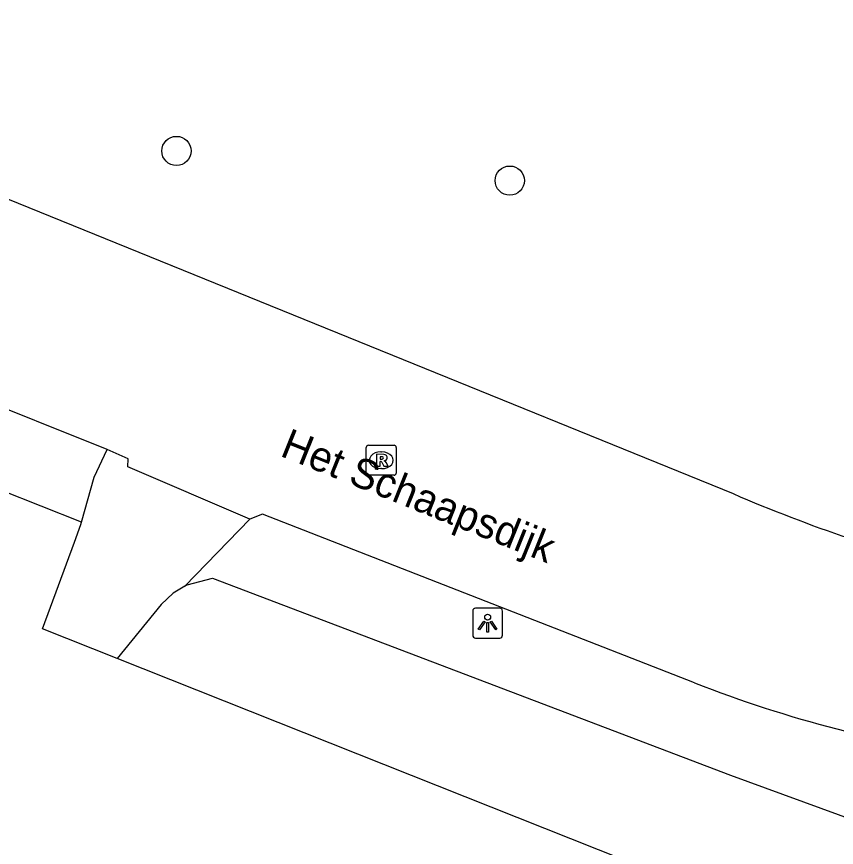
# Model space of a CAD drawing. Extents: x 156414 to 157775, y 382335 to 383765.
# Drawn here: x 156588.75 to 156616.15, y 383055.72 to 383083.48 of the extents above; entities that cross this region are included whole.
import ezdxf

# ---------------------------------------------------------------- set-up
doc = ezdxf.new("R2010")
doc.units = 0
for name, color, linetype in [('IMGEO_Boom', 7, 'Continuous'), ('IMGEO_Groenvoorziening', 7, 'Continuous'), ('IMGEO_Lichtpunt', 7, 'Continuous'), ('IMGEO_Openbare_ruimte_label', 7, 'Continuous'), ('IMGEO_Rijbaan_lokaal_gesloten', 7, 'Continuous'), ('IMGEO_Rioolput', 7, 'Continuous'), ('IMGEO_Voetpad_halfverhard', 7, 'Continuous')]:
    doc.layers.add(name, color=color, linetype=linetype)

msp = doc.modelspace()

# ---------------------------------------------------------------- linework, layer by layer
at = {"layer": 'IMGEO_Boom'}
for centre in [(156594.095, 383078.994), (156605.234, 383078.003)]:
    msp.add_circle(centre, 0.489, dxfattribs=at)
at = {"layer": 'IMGEO_Groenvoorziening'}
for points in [[(156590.919, 383066.585), (156586.871, 383068.195), (156585.286, 383064.741), (156563.007, 383025.818), (156595.152, 383012.104), (156611.363, 383016.16), (156615.246, 383017.093)], [(156594.376, 383064.451), (156594.453, 383064.497), (156595.3, 383064.715), (156612.61, 383058.128), (156628.734, 383052.234), (156630.668, 383048.465)], [(156629.772, 383039.352), (156627.811, 383047.838), (156592.108, 383062.029)]]:
    msp.add_lwpolyline(points, dxfattribs=at)
at = {"layer": 'IMGEO_Lichtpunt'}
for p, q in [((156603.995, 383063.616), (156603.995, 383062.809)), ((156603.995, 383063.616), (156603.995, 383062.809)), ((156604.897, 383063.711), (156604.089, 383063.711)), ((156604.897, 383063.711), (156604.089, 383063.711)), ((156604.991, 383062.809), (156604.991, 383063.616)), ((156604.991, 383062.809), (156604.991, 383063.616)), ((156604.089, 383062.715), (156604.897, 383062.715)), ((156604.089, 383062.715), (156604.897, 383062.715))]:
    msp.add_line(p, q, dxfattribs=at)
for points in [[(156604.369, 383063.28), (156604.408, 383063.252), (156604.22, 383062.99), (156604.182, 383063.017), (156604.369, 383063.28)], [(156604.471, 383063.232), (156604.518, 383063.232), (156604.518, 383062.91), (156604.471, 383062.91), (156604.471, 383063.232)], [(156604.581, 383063.252), (156604.619, 383063.279), (156604.806, 383063.017), (156604.767, 383062.989), (156604.581, 383063.252)]]:
    msp.add_lwpolyline(points, dxfattribs=at)
msp.add_circle((156604.494, 383063.414), 0.0994, dxfattribs=at)
for centre, start, end in [((156604.089, 383063.616), 90, 180), ((156604.089, 383063.616), 90, 180), ((156604.897, 383063.616), 0, 90), ((156604.897, 383063.616), 0, 90), ((156604.089, 383062.809), 180, 270), ((156604.089, 383062.809), 180, 270), ((156604.897, 383062.809), 270, 0), ((156604.897, 383062.809), 270, 360)]:
    msp.add_arc(centre, 0.0946, start, end, dxfattribs=at)
at = {"layer": 'IMGEO_Rijbaan_lokaal_gesloten'}
for points in [[(156573.541, 383083.485), (156575.164, 383082.79), (156612.694, 383067.543)], [(156591.78, 383069.021), (156572.654, 383076.683)], [(156596.551, 383066.686), (156592.473, 383068.437), (156592.486, 383068.704), (156591.78, 383069.021)], [(156611.409, 383061.219), (156596.972, 383066.858), (156596.551, 383066.686)]]:
    msp.add_lwpolyline(points, dxfattribs=at)
for centre, radius, start, end in [((156632.858, 383114.202), 50.83, 246.6277, 256.0191), ((156626.44, 383099.481), 41.109, 248.5523, 262.4892)]:
    msp.add_arc(centre, radius, start, end, dxfattribs=at)
at = {"layer": 'IMGEO_Rioolput'}
for p, q in [((156600.438, 383068.231), (156600.438, 383069.083)), ((156600.513, 383069.157), (156601.365, 383069.157)), ((156601.439, 383069.083), (156601.439, 383068.231)), ((156600.926, 383068.937), (156600.951, 383068.937)), ((156600.949, 383068.377), (156600.924, 383068.377)), ((156601.365, 383068.157), (156600.513, 383068.157))]:
    msp.add_line(p, q, dxfattribs=at)
for points in [[(156600.438, 383068.231), (156600.438, 383069.083)], [(156600.513, 383069.157), (156601.365, 383069.157)], [(156601.439, 383069.083), (156601.439, 383068.231)], [(156601.027, 383068.855), (156600.775, 383068.857), (156600.775, 383068.457)], [(156600.953, 383068.776), (156600.899, 383068.776), (156600.899, 383068.695)], [(156600.775, 383068.457), (156600.899, 383068.457), (156600.899, 383068.619), (156600.91, 383068.619)], [(156600.899, 383068.695), (156600.951, 383068.695)], [(156600.957, 383068.59), (156601.028, 383068.457), (156601.168, 383068.457), (156601.103, 383068.583)], [(156601.365, 383068.157), (156600.513, 383068.157)]]:
    msp.add_lwpolyline(points, dxfattribs=at)
for centre, radius, start, end in [((156600.515, 383069.081), 0.0765, 91.552, 178.448), ((156600.515, 383069.081), 0.0765, 91.552, 178.448), ((156601.363, 383069.081), 0.0765, 1.552, 88.448), ((156601.363, 383069.081), 0.0765, 1.552, 88.448), ((156600.959, 383068.68), 0.0964, 77.0061, 93.1865), ((156600.973, 383068.737), 0.0378, 276.6634, 79.6772), ((156601.026, 383068.745), 0.109, 350.3612, 89.416), ((156601.024, 383068.745), 0.112, 277.5842, 350.9817), ((156600.909, 383068.566), 0.0533, 26.0293, 88.6989), ((156600.935, 383068.884), 0.19, 274.7715, 282.9687), ((156601.008, 383068.53), 0.108, 29.5134, 73.7905), ((156600.515, 383068.233), 0.0765, 181.552, 268.448), ((156600.515, 383068.233), 0.0765, 181.552, 268.448), ((156601.363, 383068.233), 0.0765, 271.552, 358.448), ((156601.363, 383068.233), 0.0765, 271.552, 358.448)]:
    msp.add_arc(centre, radius, start, end, dxfattribs=at)
for centre, major_axis, ratio, start_param, end_param in [((156600.925, 383068.657), (-0.387, 0.002), 0.722429, 4.712389, 7.853982), ((156600.95, 383068.657), (-0.39, 0.002), 0.717154, 1.570796, 4.712389)]:
    msp.add_ellipse(centre, major_axis=major_axis, ratio=ratio, start_param=start_param, end_param=end_param, dxfattribs=at)
at = {"layer": 'IMGEO_Voetpad_halfverhard'}
for points in [[(156590.919, 383066.585), (156591.348, 383068.093), (156591.78, 383069.021)], [(156592.108, 383062.029), (156589.615, 383063.02), (156590.683, 383065.925), (156590.898, 383066.511), (156590.919, 383066.585)], [(156596.551, 383066.686), (156594.376, 383064.451)], [(156594.376, 383064.451), (156593.98, 383064.217), (156593.58, 383063.841), (156592.108, 383062.029)]]:
    msp.add_lwpolyline(points, dxfattribs=at)

# ---------------------------------------------------------------- texts
at = {"layer": 'IMGEO_Openbare_ruimte_label'}
msp.add_text('Het Schaapsdijk', height=1, rotation=338.1028, dxfattribs=at).set_placement((156597.52, 383068.814))

doc.saveas('drawing.dxf')
